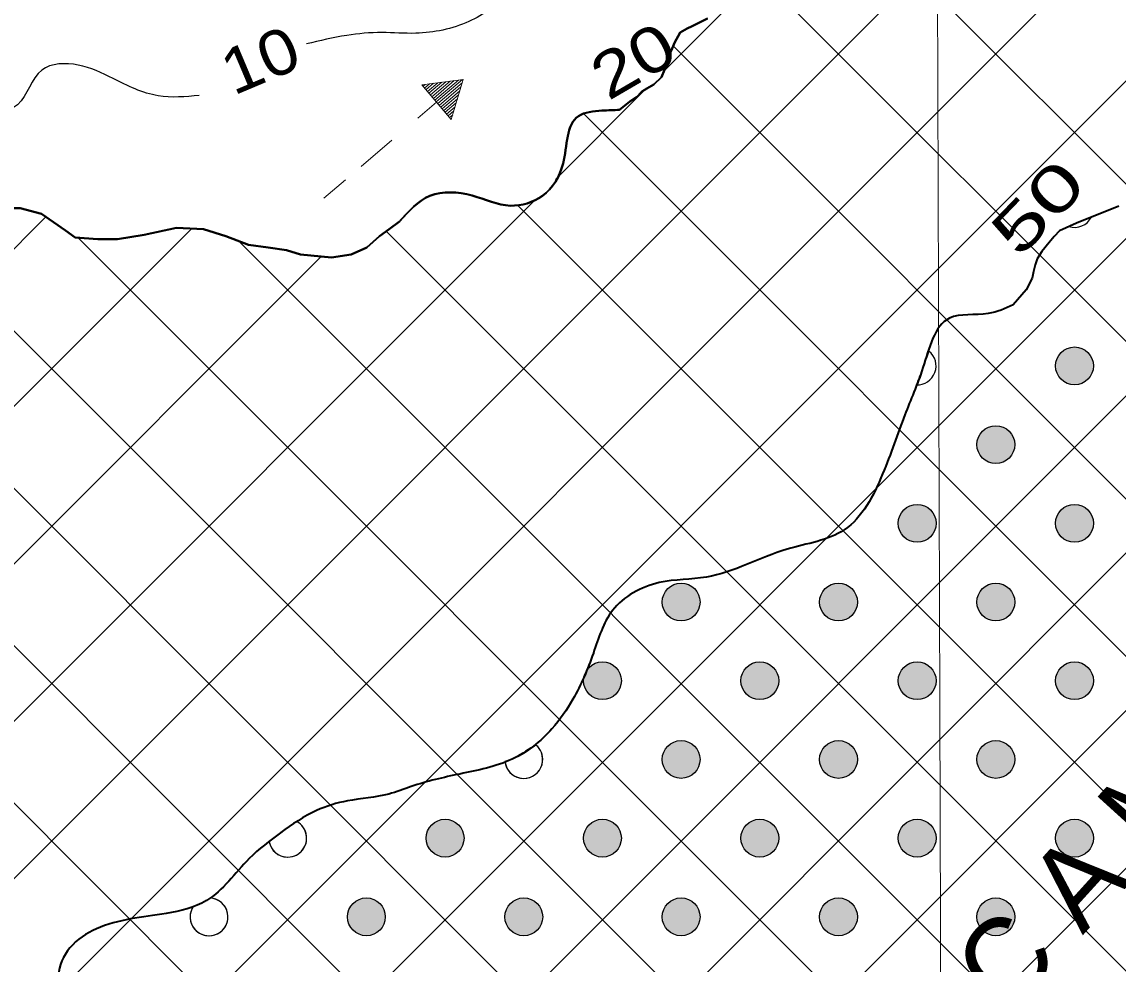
# Model space of a CAD drawing. Extents: x -10.5 to 30.8, y 18.4 to 58.7.
# Drawn here: x 11.148 to 16.073, y 37.383 to 41.615 of the extents above; entities that cross this region are included whole.
import ezdxf

# ---------------------------------------------------------------- set-up
doc = ezdxf.new("R2010")
doc.units = 0
doc.header["$LTSCALE"] = 0.08
doc.linetypes.add('DASH_DOUBLE_DOT', pattern=[9.2, 5, -1.2, 0.3, -1.2, 0.3, -1.2])
for name, color, linetype, lineweight in [('10', 7, 'Continuous', 35), ('17', 7, 'Continuous', 13), ('19', 7, 'DASH_DOUBLE_DOT', 53), ('21', 7, 'Continuous', 25), ('22', 7, 'Continuous', 25), ('47', 7, 'Continuous', 25), ('48', 7, 'Continuous', 35), ('52', 7, 'Continuous', 13), ('8', 7, 'Continuous', 25)]:
    doc.layers.add(name, color=color, linetype=linetype, lineweight=lineweight)

msp = doc.modelspace()

# ---------------------------------------------------------------- hatches: boundary and pattern name
at = {"layer": '22'}
for points in [[(15.93771, 40.13003, 1), (15.8175, 40.00982, 1)], [(15.58416, 39.77648, 1), (15.46395, 39.65627, 1)], [(15.2306, 39.42292, 1), (15.1104, 39.30272, 1)], [(15.93771, 39.42292, 1), (15.8175, 39.30272, 1)], [(14.16994, 39.06937, 1), (14.04973, 38.94916, 1)], [(14.87705, 39.06937, 1), (14.75684, 38.94916, 1)], [(15.58416, 39.06937, 1), (15.46395, 38.94916, 1)], [(13.81639, 38.71582, 1), (13.69618, 38.59561, 1)], [(14.5235, 38.71582, 1), (14.40329, 38.59561, 1)], [(15.2306, 38.71582, 1), (15.1104, 38.59561, 1)], [(15.93771, 38.71582, 1), (15.8175, 38.59561, 1)], [(14.16994, 38.36226, 1), (14.04973, 38.24206, 1)], [(14.87705, 38.36226, 1), (14.75684, 38.24206, 1)], [(15.58416, 38.36226, 1), (15.46395, 38.24206, 1)], [(13.10928, 38.00871, 1), (12.98907, 37.8885, 1)], [(13.81639, 38.00871, 1), (13.69618, 37.8885, 1)], [(14.5235, 38.00871, 1), (14.40329, 37.8885, 1)], [(15.2306, 38.00871, 1), (15.1104, 37.8885, 1)], [(15.93771, 38.00871, 1), (15.8175, 37.8885, 1)], [(12.75573, 37.65516, 1), (12.63552, 37.53495, 1)], [(13.46284, 37.65516, 1), (13.34263, 37.53495, 1)], [(14.16994, 37.65516, 1), (14.04973, 37.53495, 1)], [(14.87705, 37.65516, 1), (14.75684, 37.53495, 1)], [(15.58416, 37.65516, 1), (15.46395, 37.53495, 1)]]:
    msp.add_hatch(color=256, dxfattribs=at).paths.add_polyline_path(points)

# ---------------------------------------------------------------- linework, layer by layer
at = {"layer": '10'}
for points in [[(14.22808, 41.62986), (14.15871, 41.59644), (14.13668, 41.58543), (14.10585, 41.56781), (14.07942, 41.52155), (14.0662, 41.48851), (14.05078, 41.45546), (14.03536, 41.4004), (14.02215, 41.36735), (13.98691, 41.33431), (13.95607, 41.31669), (13.93184, 41.30127), (13.90982, 41.27704), (13.87898, 41.25721), (13.83312, 41.22019)], [(12.8447, 40.71937), (12.79801, 40.68413), (12.75373, 40.65249), (12.69679, 40.60188), (12.6272, 40.57025), (12.53863, 40.55759), (12.39944, 40.57025), (12.33618, 40.58923), (12.25393, 40.60188), (12.16536, 40.61453), (12.06414, 40.65249), (11.96291, 40.68413), (11.84271, 40.69045), (11.6972, 40.65882), (11.577, 40.63984), (11.48843, 40.63984), (11.3872, 40.64617), (11.34292, 40.6778), (11.23537, 40.75372), (11.14047, 40.77903), (11.00129, 40.77903), (10.90639, 40.76638), (10.82415, 40.75372), (10.74881, 40.71409)]]:
    msp.add_lwpolyline(points, dxfattribs=at)
msp.add_spline([(13.83312, 41.22019), (13.75409, 41.21652), (13.6482, 41.19242), (13.57947, 40.97883), (13.48622, 40.8339), (13.34297, 40.78957), (13.17049, 40.83496), (12.98099, 40.83349), (12.8447, 40.71937)], degree=3, dxfattribs=at)
at = {"layer": '17'}
for p, q in [((13.13043, 41.35665), (12.94443, 41.33266)), ((13.01077, 41.25476), (12.94443, 41.33266)), ((12.95007, 41.32604), (12.96024, 41.3347)), ((12.9567, 41.31825), (12.97884, 41.3371)), ((12.96333, 41.31046), (12.99744, 41.3395)), ((12.96997, 41.30267), (13.01604, 41.3419)), ((12.9766, 41.29488), (13.03464, 41.3443)), ((12.98324, 41.28709), (13.05324, 41.3467)), ((12.98987, 41.2793), (13.07184, 41.3491)), ((12.99651, 41.27151), (13.09044, 41.35149)), ((13.00314, 41.26371), (13.10904, 41.35389)), ((13.00978, 41.25592), (13.12764, 41.35629)), ((13.01641, 41.24813), (13.12589, 41.34137)), ((13.02305, 41.24034), (13.12056, 41.32339)), ((13.02968, 41.23255), (13.11523, 41.30541)), ((13.03632, 41.22476), (13.1099, 41.28743)), ((12.9271, 41.1835), (13.01077, 41.25476)), ((13.04295, 41.21697), (13.10457, 41.26945)), ((13.04958, 41.20918), (13.09924, 41.25146)), ((13.05622, 41.20139), (13.09391, 41.23348)), ((13.06285, 41.1936), (13.08858, 41.2155)), ((13.06949, 41.18581), (13.08325, 41.19752)), ((13.07612, 41.17802), (13.07792, 41.17954)), ((12.67193, 40.9662), (12.80989, 41.08369)), ((12.50437, 40.82351), (12.60157, 40.90628))]:
    msp.add_line(p, q, dxfattribs=at)
msp.add_lwpolyline([(13.01077, 41.25476), (13.07712, 41.17685), (13.13043, 41.35665)], dxfattribs=at)
at = {"layer": '19'}
for centre, radius, start, end in [((-10.02586, 61.06832), 35.53871, 298.19382, 343.49395), ((-10.0428, 60.19451), 39.81815, 297.24377, 345.91847)]:
    msp.add_arc(centre, radius, start, end, dxfattribs=at)
at = {"layer": '21'}
for p, q in [((6.23002, 31.47088), (23.76015, 49.00102)), ((6.44602, 30.97978), (23.814, 48.34776)), ((7.27969, 31.10634), (23.6624, 47.48905)), ((7.74396, 30.8635), (23.86242, 46.98196)), ((8.17517, 30.5876), (24.12854, 46.54098)), ((8.48205, 30.18737), (24.15516, 45.86049)), ((5.64512, 31.59308), (17.61691, 43.56488)), ((4.92807, 31.58314), (15.88709, 42.54216)), ((14.03347, 41.39565), (15.17547, 42.53765)), ((18.64069, 38.35454), (14.67805, 42.31718)), ((18.29911, 37.98901), (14.42513, 41.86299)), ((18.63254, 36.94847), (14.07372, 41.5073)), ((13.54521, 40.90739), (13.95177, 41.31395)), ((18.37132, 36.50259), (13.67204, 41.20186)), ((4.57787, 31.94005), (13.45538, 40.81756)), ((17.86431, 36.30249), (13.37432, 40.79248)), ((4.43343, 33.91693), (11.2558, 40.7393)), ((4.25704, 33.03344), (11.91049, 40.68689)), ((16.66733, 34.67104), (10.6758, 40.66257)), ((16.7729, 35.27258), (11.40012, 40.64536)), ((17.63754, 35.82215), (12.78492, 40.67478)), ((17.20459, 35.548), (12.12167, 40.63092)), ((3.98259, 32.05187), (12.4925, 40.56179)), ((16.1833, 34.44796), (10.10034, 40.53093)), ((15.6684, 34.25576), (9.56955, 40.35461)), ((15.19159, 34.02546), (9.06974, 40.14732))]:
    msp.add_line(p, q, dxfattribs=at)
for points in [[(14.22808, 41.62986), (14.15871, 41.59644), (14.13668, 41.58543), (14.10585, 41.56781), (14.07942, 41.52155), (14.0662, 41.48851), (14.05078, 41.45546), (14.03536, 41.4004), (14.02215, 41.36735), (13.98691, 41.33431), (13.95607, 41.31669), (13.93184, 41.30127), (13.90982, 41.27704), (13.87898, 41.25721), (13.83312, 41.22019)], [(12.8447, 40.71937), (12.79801, 40.68413), (12.75373, 40.65249), (12.69679, 40.60188), (12.6272, 40.57025), (12.53863, 40.55759), (12.39944, 40.57025), (12.33618, 40.58923), (12.25393, 40.60188), (12.16536, 40.61453), (12.06414, 40.65249), (11.96291, 40.68413), (11.84271, 40.69045), (11.6972, 40.65882), (11.577, 40.63984), (11.48843, 40.63984), (11.3872, 40.64617), (11.34292, 40.6778), (11.23537, 40.75372), (11.14047, 40.77903), (11.00129, 40.77903), (10.90639, 40.76638), (10.82415, 40.75372), (10.74881, 40.71409)]]:
    msp.add_lwpolyline(points, dxfattribs=at)
msp.add_spline([(13.83312, 41.22019), (13.75409, 41.21652), (13.6482, 41.19242), (13.57947, 40.97883), (13.48622, 40.8339), (13.34297, 40.78957), (13.17049, 40.83496), (12.98099, 40.83349), (12.8447, 40.71937)], degree=3, dxfattribs=at)
at = {"layer": '22', "lineweight": 35}
msp.add_line((16.07654, 40.78824), (15.88591, 40.7116), dxfattribs=at)
at = {"layer": '22'}
msp.add_line((15.16665, 39.98501), (15.16665, 39.98501), dxfattribs=at)
msp.add_lwpolyline([(15.95351, 40.73878), (15.88591, 40.7116), (15.85156, 40.69612)], dxfattribs=at)
at = {"layer": '22', "lineweight": 35}
msp.add_lwpolyline([(15.88591, 40.7116), (15.80983, 40.67731), (15.78655, 40.65071), (15.76328, 40.6241), (15.73002, 40.58419), (15.71007, 40.55093), (15.70009, 40.52433), (15.69344, 40.49439), (15.68679, 40.46446), (15.66018, 40.41125), (15.60219, 40.34391)], dxfattribs=at)
at = {"layer": '22'}
for centre in [(15.87761, 40.06993), (15.52405, 39.71637), (15.1705, 39.36282), (15.87761, 39.36282), (14.10984, 39.00927), (14.81695, 39.00927), (15.52405, 39.00927), (13.75629, 38.65571), (14.46339, 38.65571), (15.1705, 38.65571), (15.87761, 38.65571), (14.10984, 38.30216), (14.81695, 38.30216), (15.52405, 38.30216), (13.04918, 37.94861), (13.75629, 37.94861), (14.46339, 37.94861), (15.1705, 37.94861), (15.87761, 37.94861), (12.69563, 37.59505), (13.40273, 37.59505), (14.10984, 37.59505), (14.81695, 37.59505), (15.52405, 37.59505)]:
    msp.add_circle(centre, 0.085, dxfattribs=at)
for centre, start, end in [((15.87761, 40.77703), 252.15778, 333.25301), ((15.87761, 40.77703), 252.15778, 333.25299), ((15.1705, 40.06993), 267.40787, 51.58913), ((15.1705, 40.06993), 267.40787, 51.58913), ((13.40273, 38.30216), 185.80147, 49.78372), ((13.40273, 38.30216), 297.79259, 49.76886), ((13.40273, 38.30216), 186.10327, 297.7926), ((12.34207, 37.94861), 191.06172, 61.98557), ((12.34207, 37.94861), 306.52364, 61.98557), ((12.34207, 37.94861), 191.06172, 306.52364), ((11.98852, 37.59505), 145.89144, 86.71611), ((11.98852, 37.59505), 146.90766, 246.16633), ((11.98852, 37.59505), 246.16633, 85.58875)]:
    msp.add_arc(centre, 0.085, start, end, dxfattribs=at)
at = {"layer": '22', "lineweight": 35}
msp.add_spline([(15.60219, 40.34391), (15.49008, 40.30537), (15.31539, 40.28452), (15.19648, 40.06244), (15.11481, 39.84971), (15.01541, 39.58503), (14.84269, 39.33312), (14.58651, 39.24653), (14.22348, 39.12125), (14.01175, 39.09629), (13.80158, 38.97153), (13.71543, 38.77994), (13.62342, 38.57278), (13.52887, 38.4392), (13.34991, 38.30298), (13.11556, 38.23672), (12.89739, 38.18047), (12.79601, 38.14685), (12.6104, 38.11583), (12.47178, 38.07287), (12.30997, 37.97287), (12.16862, 37.85648), (11.97718, 37.66815), (11.79587, 37.61075), (11.48236, 37.54169), (11.36324, 37.45612), (11.3112, 37.33172), (11.31081, 37.32123), (11.211, 37.18782), (11.03319, 37.08306), (10.95638, 37.00143), (10.88348, 36.88293), (10.75655, 36.87111), (10.6351, 36.72261), (10.5579, 36.63049), (10.50121, 36.54526)], degree=3, dxfattribs=at)
at = {"layer": '22'}
for points in [[(15.22331, 40.13653), (15.19648, 40.06244), (15.16665, 39.98501)], [(13.45763, 38.36705), (13.34991, 38.30298), (13.31821, 38.29312)], [(12.382, 38.02365), (12.30997, 37.97287), (12.25865, 37.9323)], [(11.99506, 37.6798), (11.97718, 37.66815), (11.91731, 37.64146)]]:
    msp.add_spline(points, degree=3, dxfattribs=at)
at = {"layer": '48'}
for points in [[(13.83312, 41.22019), (13.87898, 41.25721), (13.90982, 41.27704), (13.93184, 41.30127), (13.95607, 41.31669), (13.98691, 41.33431), (14.02215, 41.36735), (14.03536, 41.4004), (14.05078, 41.45546), (14.0662, 41.48851), (14.07942, 41.52155), (14.10585, 41.56781), (14.13668, 41.58543), (14.15871, 41.59644), (14.22808, 41.62986)], [(10.74881, 40.71409), (10.82415, 40.75372), (10.90639, 40.76638), (11.00129, 40.77903), (11.14047, 40.77903), (11.23537, 40.75372), (11.34292, 40.6778)], [(11.34292, 40.6778), (11.3872, 40.64617), (11.48843, 40.63984), (11.577, 40.63984), (11.6972, 40.65882), (11.84271, 40.69045), (11.96291, 40.68413), (12.06414, 40.65249), (12.16536, 40.61453), (12.25393, 40.60188), (12.33618, 40.58923), (12.39944, 40.57025), (12.53863, 40.55759), (12.6272, 40.57025), (12.69679, 40.60188), (12.75373, 40.65249), (12.79801, 40.68413), (12.8447, 40.71937)]]:
    msp.add_lwpolyline(points, dxfattribs=at)
msp.add_spline([(12.8447, 40.71937), (12.98099, 40.83349), (13.17049, 40.83496), (13.34297, 40.78957), (13.48622, 40.8339), (13.57947, 40.97883), (13.6482, 41.19242), (13.75409, 41.21652), (13.83312, 41.22019)], degree=3, dxfattribs=at)
at = {"layer": '52'}
msp.add_lwpolyline([(15.21021, 58.74412), (15.22114, 55.15419), (15.238, 49.61911), (15.25486, 44.08411), (15.27173, 38.54878), (15.28859, 33.01269), (15.30545, 27.4754), (15.32144, 22.22646)], dxfattribs=at)
at = {"layer": '8'}
msp.add_lwpolyline([(10.74881, 40.71409), (10.82415, 40.75372), (10.90639, 40.76638), (11.00129, 40.77903), (11.14047, 40.77903), (11.23537, 40.75372), (11.34292, 40.6778), (11.3872, 40.64617), (11.48843, 40.63984), (11.577, 40.63984), (11.6972, 40.65882), (11.84271, 40.69045), (11.96291, 40.68413), (12.06414, 40.65249), (12.16536, 40.61453), (12.25393, 40.60188), (12.33618, 40.58923), (12.39944, 40.57025), (12.53863, 40.55759), (12.6272, 40.57025), (12.69679, 40.60188), (12.75373, 40.65249), (12.79801, 40.68413), (12.8447, 40.71937)], dxfattribs=at)
for points in [[(15.97655, 44.2216), (15.87944, 43.93774), (15.87369, 43.71766), (15.90169, 43.58078), (15.95722, 43.49055), (16.09801, 43.44055), (16.25956, 43.37966), (16.31802, 43.20023), (16.15749, 43.09858), (15.93104, 43.09262), (15.75179, 43.08046), (15.43633, 43.092), (15.11575, 43.10889), (14.90672, 43.16549), (14.79571, 43.14673), (14.72876, 43.00126), (14.45873, 42.9385), (14.31343, 42.81557), (14.19845, 42.64485), (14.02507, 42.45432), (13.84889, 42.35822), (13.66772, 42.27271), (13.50056, 42.11876), (13.44522, 42.01501), (13.34923, 41.76527), (13.25209, 41.67284), (13.1559, 41.61709), (12.9177, 41.56417), (12.76517, 41.56721), (12.60695, 41.55464), (12.42702, 41.51629)], [(11.94445, 41.28477), (11.76022, 41.2832), (11.557, 41.36066), (11.4007, 41.42144), (11.23696, 41.3985), (11.12765, 41.24339), (10.99506, 41.2041), (10.76096, 41.30838), (10.62722, 41.4264), (10.57462, 41.42744), (10.50446, 41.36069), (10.28968, 41.1972), (10.09786, 41.10666), (9.94963, 41.07292), (9.67611, 41.07838), (9.55249, 41.01473)], [(13.83312, 41.22019), (13.75409, 41.21652), (13.6482, 41.19242), (13.57947, 40.97883), (13.48622, 40.8339), (13.34297, 40.78957), (13.17049, 40.83496), (12.98099, 40.83349), (12.83871, 40.71409)], [(15.8921, 40.71409), (16.06923, 40.7853), (15.88733, 40.71217)], [(15.60219, 40.34391), (15.49008, 40.30537), (15.31539, 40.28452), (15.19648, 40.06244), (15.11481, 39.84971), (15.01541, 39.58503), (14.84269, 39.33312), (14.58651, 39.24653), (14.22348, 39.12125), (14.01175, 39.09629), (13.80158, 38.97153), (13.71543, 38.77994), (13.62342, 38.57278), (13.52887, 38.4392), (13.34991, 38.30298), (13.11556, 38.23672), (12.89739, 38.18047), (12.79601, 38.14685), (12.6104, 38.11583), (12.47178, 38.07287), (12.30997, 37.97287), (12.16862, 37.85648), (11.97718, 37.66815), (11.79587, 37.61075), (11.48236, 37.54169), (11.36324, 37.45612), (11.3112, 37.33172), (11.31081, 37.32123), (11.211, 37.18782), (11.03319, 37.08306), (10.95638, 37.00143), (10.88348, 36.88293), (10.75655, 36.87111), (10.6351, 36.72261), (10.5579, 36.63049), (10.47525, 36.5333), (10.3376, 36.51655)]]:
    msp.add_spline(points, degree=3, dxfattribs=at)

# ---------------------------------------------------------------- texts
at = {"layer": '47'}
msp.add_text('B A C I A   D E  C A M P O S ', height=0.3694, rotation=47.766, dxfattribs=at).set_placement((13.20184, 34.5238))
at = {"layer": '8'}
for s, rotation, width, p in [('10', 22.872, 1.15, (12.0978, 41.28258)), ('20', 30.246, 1.25, (13.78235, 41.2584)), ('50', 46.175, 1.5, (15.62867, 40.54864))]:
    msp.add_text(s, height=0.2032, rotation=rotation, dxfattribs=dict(at, width=width)).set_placement(p)

doc.saveas('drawing.dxf')
